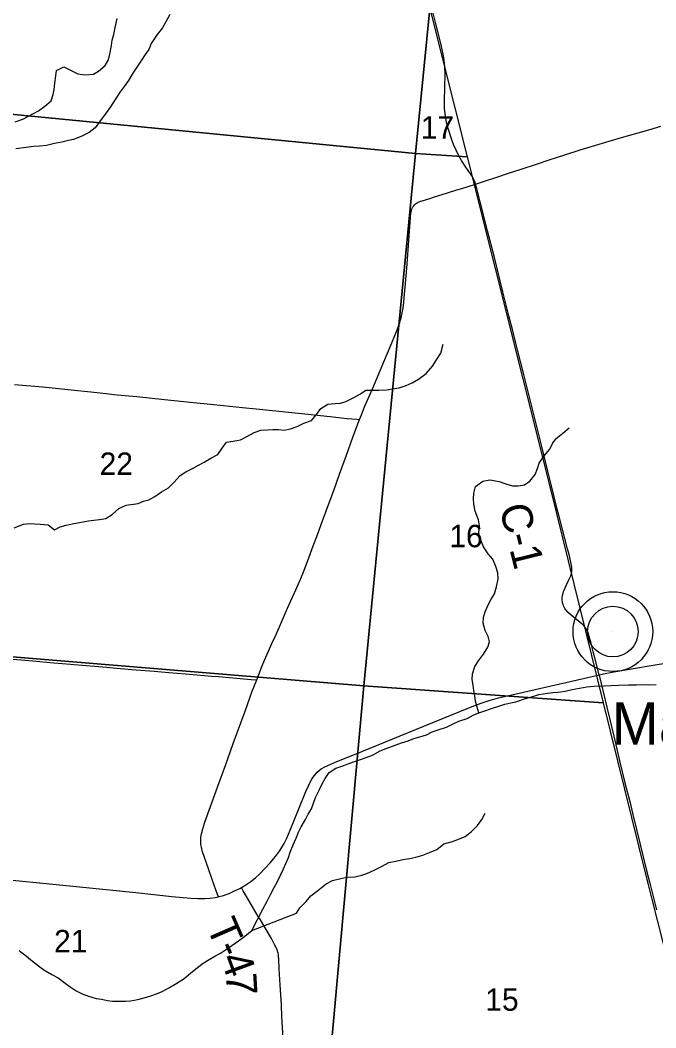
# Model space of a CAD drawing. Extents: x 0 to 1101, y 0 to 440.
# Drawn here: x 264.9 to 300.5, y 282.9 to 339.3 of the extents above; entities that cross this region are included whole.
import ezdxf

# ---------------------------------------------------------------- set-up
doc = ezdxf.new("R2010")
doc.units = 0
for name, color, linetype in [('GM_X_County_Road', 7, 'Continuous'), ('GM_X_County_Road_Text', 7, 'Continuous'), ('GM_X_Major_River', 7, 'Continuous'), ('GM_X_Minor_River', 7, 'Continuous'), ('GM_X_Section', 7, 'Continuous'), ('GM_X_Section_Text', 7, 'Continuous'), ('GM_X_State_Route', 7, 'Continuous'), ('GM_X_Township_Road', 7, 'Continuous'), ('GM_X_Township_Road_Text', 7, 'Continuous'), ('GM_X_Unincorporated', 7, 'Continuous'), ('GM_X_Unincorporated_Location', 7, 'Continuous'), ('GM_X_Unincorporated_Text', 7, 'Continuous')]:
    doc.layers.add(name, color=color, linetype=linetype)

msp = doc.modelspace()

# ---------------------------------------------------------------- linework, layer by layer
at = {"layer": 'GM_X_County_Road'}
for points in [[(295.789, 308.778), (295.782, 308.825), (295.748, 309.008), (295.709, 309.179), (295.647, 309.429), (295.561, 309.745), (295.098, 311.551), (294.99, 311.966), (294.662, 313.28), (294.587, 313.579), (294.457, 314.098), (294.267, 314.868), (294.116, 315.475), (293.91, 316.299), (293.335, 318.6), (293.095, 319.578), (292.769, 320.879), (292.668, 321.257), (292.49, 321.943), (292.275, 322.786), (291.946, 324.122), (291.464, 326.045), (291.075, 327.544), (290.674, 329.16), (290.49, 329.908), (290.454, 330.033), (290.413, 330.163), (290.389, 330.239), (290.346, 330.349), (290.274, 330.489), (290.204, 330.615), (290.128, 330.74), (289.875, 331.106), (289.629, 331.481), (289.455, 331.777), (289.318, 332.059), (289.182, 332.377), (289.089, 332.637), (288.898, 333.206), (288.842, 333.398), (288.79, 333.598), (288.759, 333.738), (288.729, 333.904), (288.703, 334.1), (288.682, 334.388), (288.67, 334.805), (288.691, 335.624), (288.706, 336.293), (288.695, 336.72), (288.68, 336.915), (288.663, 337.078), (288.638, 337.238), (288.599, 337.437), (288.545, 337.684), (288.485, 337.945), (288.171, 339.192), (288.037, 339.716)], [(278.162, 302.412), (278.427, 303.103), (278.598, 303.516), (278.82, 304.018), (279.012, 304.451), (279.245, 304.959), (279.546, 305.641), (279.895, 306.424), (280.076, 306.834), (280.357, 307.459), (280.57, 307.96), (280.756, 308.408), (281.056, 309.191), (281.273, 309.766), (281.58, 310.587), (281.771, 311.113), (282.165, 312.179), (282.471, 313.02), (282.797, 313.932), (283.18, 314.991), (283.547, 315.999), (283.914, 316.982), (284.019, 317.25), (284.202, 317.692), (284.717, 318.876), (285.037, 319.635), (285.286, 320.217), (285.631, 321.043), (285.987, 321.905), (286.104, 322.213), (286.165, 322.396), (286.198, 322.501), (286.249, 322.673), (286.291, 322.853), (286.328, 323.04), (286.353, 323.223), (286.389, 323.537), (286.414, 323.812), (286.485, 324.592), (286.56, 325.447), (286.694, 327.25), (286.772, 328.283), (286.794, 328.513), (286.803, 328.588), (286.82, 328.666), (286.839, 328.731), (286.87, 328.811), (286.906, 328.882), (286.949, 328.948), (287.002, 329.007), (287.049, 329.05), (287.112, 329.093), (287.147, 329.113), (287.203, 329.142), (287.261, 329.166), (287.337, 329.195), (287.425, 329.225), (287.853, 329.359), (288.065, 329.428), (288.833, 329.666), (289.359, 329.83), (289.649, 329.921), (290.413, 330.163), (290.858, 330.305), (291.542, 330.529), (292.25, 330.761), (292.906, 330.977), (293.88, 331.298), (294.533, 331.513), (295.401, 331.794), (296.27, 332.072), (297.517, 332.446), (298.59, 332.769), (299.522, 333.035), (300.114, 333.203), (300.776, 333.398)], [(264.596, 318.953), (266.192, 318.806), (267.415, 318.687), (269.229, 318.49), (270.358, 318.374), (271.445, 318.266), (273.008, 318.108), (274.629, 317.942), (275.584, 317.845), (276.307, 317.774), (277.376, 317.664), (278.124, 317.587), (279.051, 317.491), (279.941, 317.399), (280.697, 317.32), (281.738, 317.205), (282.276, 317.149), (283.221, 317.051), (283.744, 316.999), (283.914, 316.982)], [(297.326, 302.702), (297.086, 303.658), (297.002, 303.988), (296.86, 304.542), (296.781, 304.848), (296.721, 305.04), (296.665, 305.174), (296.634, 305.229), (296.593, 305.298), (296.557, 305.35), (296.518, 305.398), (296.469, 305.452), (296.406, 305.514), (296.25, 305.639), (295.888, 305.928), (295.746, 306.05), (295.6, 306.188), (295.471, 306.332), (295.415, 306.407), (295.372, 306.48), (295.339, 306.553), (295.308, 306.636), (295.288, 306.719), (295.276, 306.796), (295.27, 306.869), (295.265, 306.955), (295.268, 307.025), (295.281, 307.129), (295.31, 307.276), (295.338, 307.362), (295.367, 307.431), (295.429, 307.568), (295.507, 307.728), (295.657, 308.053), (295.74, 308.246), (295.781, 308.372), (295.797, 308.455), (295.805, 308.515), (295.807, 308.582), (295.803, 308.641), (295.795, 308.731), (295.789, 308.778)], [(276.02, 290.283), (275.974, 290.41), (275.785, 290.929), (275.652, 291.296), (275.475, 291.796), (275.326, 292.214), (275.126, 292.799), (275.065, 293.049), (275.041, 293.213), (275.031, 293.395), (275.041, 293.597), (275.072, 293.796), (275.146, 294.082), (275.266, 294.459), (275.971, 296.417), (276.426, 297.685), (276.849, 298.86), (277.51, 300.662), (277.917, 301.776), (278.162, 302.412)]]:
    msp.add_lwpolyline(points, dxfattribs=at)
at = {"layer": 'GM_X_Major_River'}
for points in [[(273.305, 339.648), (273.072, 339.242), (272.885, 338.903), (272.596, 338.52)], [(272.596, 338.52), (272.259, 338.024), (272.118, 337.696), (271.92, 337.403), (271.711, 337.099), (271.421, 336.636), (271.189, 336.309), (270.99, 335.948), (270.747, 335.621), (270.527, 335.317), (270.236, 334.9), (269.98, 334.482), (269.737, 334.144), (269.354, 333.649), (269.111, 333.311), (268.789, 333.054), (268.331, 332.821), (267.908, 332.656), (267.623, 332.592), (267.246, 332.506), (266.847, 332.421), (266.391, 332.325), (266.004, 332.285), (265.662, 332.255), (265.264, 332.204), (264.683, 332.133)]]:
    msp.add_lwpolyline(points, dxfattribs=at)
at = {"layer": 'GM_X_Minor_River'}
for points in [[(264.636, 333.636), (265.07, 333.789), (265.379, 333.955), (265.941, 334.255), (266.297, 334.511), (266.665, 334.814), (266.772, 335.165), (266.822, 335.46), (266.861, 335.801), (266.912, 336.21), (266.962, 336.517), (267.374, 336.727), (267.848, 336.47), (268.153, 336.329), (268.562, 336.267), (269.017, 336.317), (269.304, 336.472), (269.683, 336.797), (269.87, 337.113), (269.942, 337.431), (270.04, 337.919), (270.079, 338.214), (270.163, 338.52), (270.236, 338.918), (270.346, 339.417)], [(274.606, 314.271), (274.904, 314.438), (275.213, 314.604), (275.603, 314.826), (275.981, 315.026), (276.225, 315.387), (276.468, 315.725), (276.844, 315.776), (277.254, 315.839), (277.655, 316.05), (278.022, 316.261), (278.388, 316.392), (278.763, 316.41), (279.07, 316.428), (279.377, 316.424), (279.695, 316.396), (280.06, 316.46), (280.426, 316.591), (280.792, 316.779), (281.227, 316.933), (281.504, 317.27), (281.748, 317.597), (282.149, 317.841), (282.559, 317.881), (282.855, 317.9), (283.152, 317.987), (283.633, 318.23), (283.965, 318.431), (284.275, 318.62), (284.559, 318.627), (284.991, 318.632), (285.446, 318.649), (285.754, 318.701), (286.142, 318.764), (286.53, 318.895), (286.873, 319.038), (287.228, 319.238), (287.642, 319.562), (288.001, 319.979), (288.233, 320.317), (288.477, 320.689), (288.598, 321.199)], [(290.591, 300.57), (290.493, 300.936), (290.418, 301.222), (290.366, 301.541), (290.324, 301.826), (290.271, 302.111), (290.219, 302.442), (290.246, 302.761), (290.377, 303.157), (290.575, 303.473), (290.865, 303.856), (291.109, 304.251), (291.193, 304.546), (291.117, 304.843), (290.952, 305.175), (290.844, 305.586), (290.848, 305.916), (290.955, 306.222), (291.12, 306.618), (291.283, 306.934), (291.47, 307.239), (291.577, 307.625), (291.686, 308.078), (291.657, 308.397), (291.548, 308.752), (291.383, 309.175), (291.126, 309.463), (290.859, 309.854), (290.672, 310.335), (290.597, 310.643), (290.625, 311.041), (290.585, 311.372), (290.387, 311.853), (290.324, 312.252), (290.306, 312.548), (290.31, 312.867), (290.418, 313.241), (290.82, 313.531), (291.208, 313.617), (291.729, 313.518), (292.103, 313.388), (292.476, 313.28), (292.795, 313.276), (293.159, 313.339), (293.446, 313.54), (293.747, 313.911), (293.889, 314.25), (293.972, 314.545), (294.262, 314.951), (294.575, 315.322), (294.716, 315.639), (294.924, 315.932), (295.304, 316.222), (295.649, 316.513)], [(264.587, 310.93), (265.113, 311.127), (265.488, 311.168), (266.034, 311.137), (266.488, 311.097), (266.836, 310.818), (267.157, 310.973), (267.499, 311.071), (267.933, 311.167), (268.446, 311.262), (268.754, 311.315), (269.038, 311.345), (269.369, 311.397), (269.722, 311.449), (270.078, 311.672), (270.446, 311.997), (270.858, 312.184), (271.519, 312.289), (271.816, 312.41), (272.125, 312.497), (272.468, 312.685), (272.824, 312.931), (273.225, 313.164), (273.514, 313.467), (273.872, 313.861), (274.193, 314.061), (274.606, 314.271)], [(277.897, 288.387), (278.508, 289.587), (278.741, 290.027), (278.929, 290.4), (279.139, 290.807), (279.326, 291.135), (279.49, 291.485), (279.665, 291.847), (279.795, 292.141), (279.947, 292.48), (280.042, 292.775), (280.196, 293.182), (280.372, 293.567), (280.502, 293.895), (280.654, 294.2), (280.887, 294.607), (281.039, 294.9), (281.237, 295.205), (281.332, 295.511), (281.45, 295.839), (281.673, 296.28), (281.825, 296.597), (282, 296.89), (282.209, 297.229), (282.588, 297.485), (283.033, 297.627), (283.319, 297.736), (283.696, 297.868), (284.085, 297.999), (284.645, 298.207), (285.08, 298.451), (285.4, 298.572), (285.915, 298.758), (286.258, 298.901), (286.634, 299.01), (286.966, 299.142), (287.297, 299.228), (287.662, 299.337), (287.983, 299.503), (288.326, 299.624), (288.783, 299.776), (289.161, 299.965), (289.481, 300.097), (289.938, 300.25), (290.282, 300.45), (290.591, 300.57), (290.876, 300.657), (291.31, 300.822), (291.71, 300.942), (292.053, 301.051), (292.383, 301.126), (292.668, 301.179), (293.217, 301.376), (293.617, 301.484), (293.948, 301.593), (294.438, 301.666), (294.745, 301.707), (295.03, 301.737), (295.429, 301.789), (295.828, 301.885), (296.238, 301.959), (296.637, 302.033), (297.058, 302.062), (297.605, 302.088), (298.003, 302.094), (298.412, 302.122), (298.981, 302.137), (299.413, 302.142), (299.766, 302.149), (300.095, 302.144), (300.527, 302.149)], [(277.897, 288.387), (280.381, 289.367), (280.578, 289.66), (280.924, 290.019), (281.201, 290.323), (281.592, 290.636), (282.052, 291.005), (282.407, 291.182), (282.864, 291.301), (283.206, 291.376), (283.65, 291.392), (284.038, 291.489), (284.335, 291.587), (284.735, 291.775), (285.193, 291.996), (285.549, 292.196), (285.959, 292.27), (286.347, 292.356), (286.734, 292.419), (287.065, 292.505), (287.453, 292.613), (287.83, 292.756), (288.254, 292.932), (288.633, 293.234), (289.124, 293.375), (289.513, 293.518), (289.822, 293.661), (290.178, 293.941), (290.524, 294.266), (290.767, 294.604), (290.943, 294.966)], [(264.874, 287.265), (265.268, 286.949), (265.617, 286.68), (265.954, 286.41), (266.247, 286.199), (266.687, 285.928), (267.048, 285.739), (267.363, 285.504), (267.712, 285.235), (268.051, 285.023), (268.39, 284.857), (268.741, 284.713), (269.184, 284.591), (269.468, 284.551), (269.809, 284.476), (270.094, 284.437), (270.516, 284.429), (270.813, 284.435), (271.099, 284.453), (271.5, 284.526), (271.856, 284.633), (272.234, 284.741), (272.545, 284.849), (272.867, 284.981), (273.282, 285.202), (273.697, 285.446), (274.102, 285.713), (274.461, 286.003), (274.855, 286.316), (275.168, 286.562), (275.492, 286.762), (275.827, 286.962), (276.126, 287.116), (276.462, 287.35), (276.774, 287.562), (277.144, 287.818), (277.492, 288.074), (277.897, 288.387)]]:
    msp.add_lwpolyline(points, dxfattribs=at)
at = {"layer": 'GM_X_Section'}
for points in [[(282.042, 362.903), (287.855, 339.988), (287.055, 331.875), (257.267, 334.765), (260.116, 364.815)], [(287.055, 331.875), (287.855, 339.988), (289.938, 331.691)], [(287.055, 331.875), (284.164, 302.086), (254.28, 304.547), (257.267, 334.765)], [(287.055, 331.875), (289.938, 331.691), (294.624, 313.009), (297.548, 301.138), (284.164, 302.086)], [(284.164, 302.086), (281.404, 271.573), (251.23, 274.522), (254.28, 304.547)], [(284.164, 302.086), (297.548, 301.138), (299.942, 291.467), (305.596, 269.192), (281.404, 271.573)]]:
    msp.add_lwpolyline(points, close=True, dxfattribs=at)
at = {"layer": 'GM_X_State_Route'}
for points in [[(297.326, 302.702), (297.567, 302.747), (298.145, 302.86), (300.359, 303.234), (302.872, 303.658)], [(262.579, 291.402), (266.011, 291.064), (270.11, 290.648), (271.39, 290.515), (273.411, 290.303), (274.469, 290.21), (274.865, 290.186), (275.067, 290.177), (275.263, 290.182), (275.548, 290.206), (275.838, 290.246), (276.02, 290.283), (276.055, 290.291), (276.305, 290.359), (276.444, 290.406), (276.619, 290.471), (276.925, 290.603), (277.212, 290.746), (277.302, 290.797), (277.409, 290.857), (277.561, 290.95), (277.836, 291.137), (278.098, 291.344), (278.346, 291.568), (278.643, 291.875), (278.913, 292.182), (279.211, 292.539), (279.434, 292.836), (279.557, 293.021), (279.696, 293.261), (279.845, 293.559), (280.035, 294.004), (280.521, 295.195), (280.92, 296.161), (281.06, 296.487), (281.175, 296.724), (281.251, 296.865), (281.316, 296.967), (281.395, 297.074), (281.465, 297.161), (281.544, 297.246), (281.652, 297.344), (281.778, 297.438), (281.981, 297.553), (282.097, 297.608), (282.517, 297.789), (284.044, 298.408), (287.513, 299.828), (289.532, 300.652), (290.311, 300.966), (290.785, 301.138), (291.177, 301.263), (291.699, 301.407), (292.444, 301.582), (294.644, 302.081), (296.533, 302.52), (297.326, 302.702), (297.333, 302.673)], [(297.333, 302.673), (297.775, 300.809), (298.144, 299.269), (298.496, 297.82), (298.777, 296.661), (299.045, 295.615), (299.224, 294.891), (299.626, 293.205), (299.986, 291.758), (300.17, 291.035), (300.389, 290.148), (300.533, 289.55)]]:
    msp.add_lwpolyline(points, dxfattribs=at)
at = {"layer": 'GM_X_Township_Road'}
for points in [[(264.511, 303.57), (265.625, 303.473), (266.806, 303.369), (267.734, 303.292), (268.161, 303.255), (269.747, 303.125), (270.126, 303.094), (271.18, 303.006), (272.414, 302.899), (273.237, 302.831), (274.179, 302.752), (274.809, 302.698), (275.242, 302.663), (275.644, 302.63), (276.017, 302.601), (276.819, 302.537), (277.853, 302.442), (278.162, 302.412)], [(279.643, 282.361), (279.572, 283.589), (279.541, 284.231), (279.475, 285.343), (279.428, 286.254), (279.397, 286.812), (279.389, 286.93), (279.376, 287.057), (279.363, 287.125), (279.346, 287.187), (279.324, 287.257), (279.29, 287.344), (279.231, 287.478), (279.186, 287.573), (279.126, 287.688), (278.984, 287.951), (278.7, 288.446), (278.366, 288.983), (278.251, 289.174), (277.771, 289.972), (277.406, 290.614), (277.302, 290.797)]]:
    msp.add_lwpolyline(points, dxfattribs=at)
at = {"layer": 'GM_X_Unincorporated'}
for radius in [2.232, 1.415]:
    msp.add_circle((298.1, 305.117), radius, dxfattribs=at)
at = {"layer": 'GM_X_Unincorporated_Location'}
msp.add_line((298.1, 305.117), (298.1, 305.117), dxfattribs=at)

# ---------------------------------------------------------------- texts
at = {"layer": 'GM_X_County_Road_Text'}
msp.add_text('C-1', height=1.7045, rotation=283.9242, dxfattribs=at).set_placement((291.732, 312.073))
at = {"layer": 'GM_X_Section_Text'}
for s, p in [('17', (287.344, 332.703)), ('22', (269.369, 313.884)), ('16', (288.944, 309.838)), ('21', (266.819, 287.172)), ('15', (290.956, 283.903))]:
    msp.add_text(s, height=1.2557, rotation=0, dxfattribs=at).set_placement(p)
at = {"layer": 'GM_X_Township_Road_Text'}
for s, rotation, p in [('T', 293.617, (275.321, 288.625)), ('-', 293.5266, (275.831, 287.457)), ('4', 290.0462, (276.101, 286.841)), ('7', 273.4992, (276.434, 285.982))]:
    msp.add_text(s, height=1.705, rotation=rotation, dxfattribs=at).set_placement(p)
at = {"layer": 'GM_X_Unincorporated_Text'}
msp.add_text('Macochee Castle', height=2.36932, rotation=0, dxfattribs=at).set_placement((298.031, 298.785))

doc.saveas('drawing.dxf')
